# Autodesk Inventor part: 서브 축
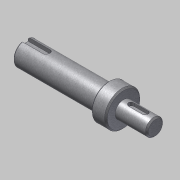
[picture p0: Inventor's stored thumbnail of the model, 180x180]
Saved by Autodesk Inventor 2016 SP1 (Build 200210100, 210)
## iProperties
Created: 2016-04
Part Number: 서브 축
Document SubType Name: Modeling
Designer: mdu
Density: 7.86 g/cm^3
Mass: 163.127 g
Surface Area: 58.4714 cm^2
Volume: 20.754 cm^3
Material: 강철, 연강
Appearance: 금속-강(스테인리스, 브러시됨)
Author: mdu
Revision Number: 1
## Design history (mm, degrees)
sketch "스케치1"
  geometry: L1 (-16.331, 0)-(-108.831, 0); L2 (-16.331, 0)-(-16.331, -6); L3 (-16.331, -6)-(-38.831, -6); L4 (-38.831, -12.5)-(-46.5, -12.5); L5 (-46.5, -8.5)-(-108.831, -8.5); L6 (-108.831, -8.5)-(-108.831, 0); L7 (-46.5, -8.5)-(-46.5, -12.5); L8 (-38.831, -6)-(-38.831, -12.5); L9 (-46.5, 12.249)-(-46.5, -12.249) reference; L10 (-38.831, -17)-(-38.831, 17) reference; 2 further points
  constraints: 17 end point, 4 perpendicular, 2 collinear, 2 parallel, 1 horizontal, 1 midpoint, 1 point on line
  dimensions: "d1" = 12 diameter of L3 L1; "d2" = 25 diameter of L4 L1; "d3" = 17 diameter of L5 L1; "d18" = 22.5 distance of L2.end L3.end; "d20" = 70 distance between parallel lines of L6 L8; "d21" = 7.66872 distance of L4.start L4.end (derived)
revolve "회전1" sketch "스케치1" stored, may be unused: angle "d5" = 90 deg
chamfer "모따기1" distance "d6" = 1; stored, may be unused: second distance "d7" = 2, angle "d8" = 45 deg
node "작업 평면1"
sketch "스케치2"
  geometry: L1 (11.25, 5)-(11.25, -5) reference; L2 (-5.75, -2)-(4.25, -2); L3 (4.25, 2)-(-5.75, 2); A1 r 2 centre (4.25, 0) between (4.25, -2) and (4.25, 2); A2 r 2 centre (-5.75, 0) between (-5.75, 2) and (-5.75, -2); 2 further points
  constraints: 4 end point, 4 point on circle, 4 tangent, 2 centre point, 1 horizontal alignment, 1 midpoint, 1 parallel, 1 perpendicular
  dimensions: "d9" = 4 distance between parallel lines of L2 L3; "d10" = 14 dimension on A1 A2; "d11" = 5 distance edge to line of A1 L1
extrude "돌출1" cut sketch "스케치2" distance "d12" = 2.5; taper "d13" = 0 deg
node "작업 평면2"
sketch "스케치3"
  geometry: L1 (-31.166, -7.5)-(-31.166, 7.5) reference; L2 (-31.166, 2.5)-(-15.666, 2.5); L3 (-15.666, -2.5)-(-31.166, -2.5); A1 r 2.5 centre (-15.666, 0) between (-15.666, -2.5) and (-15.666, 2.5); 2 further points
  constraints: 4 end point, 2 perpendicular, 2 point on circle, 2 point on line, 2 tangent, 1 centre point, 1 horizontal alignment, 1 midpoint
  dimensions: "d14" = 5 distance between parallel lines of L3 L2; "d15" = 18 dimension on A1 L1
extrude "돌출2" cut sketch "스케치3" distance "d16" = 3; taper "d17" = 0 deg
sketch "스케치4"
  geometry: C1 r 12.5 at (0, 0) reference; 1 further point
extrude "돌출3" join sketch "스케치4" distance "d22" = 3; taper "d23" = 0 deg
chamfer "모따기2" distance "d24" = 1; stored, may be unused: second distance "d25" = 2, angle "d26" = 45 deg
node "솔리드1"
node "참조4"
node "참조5"
